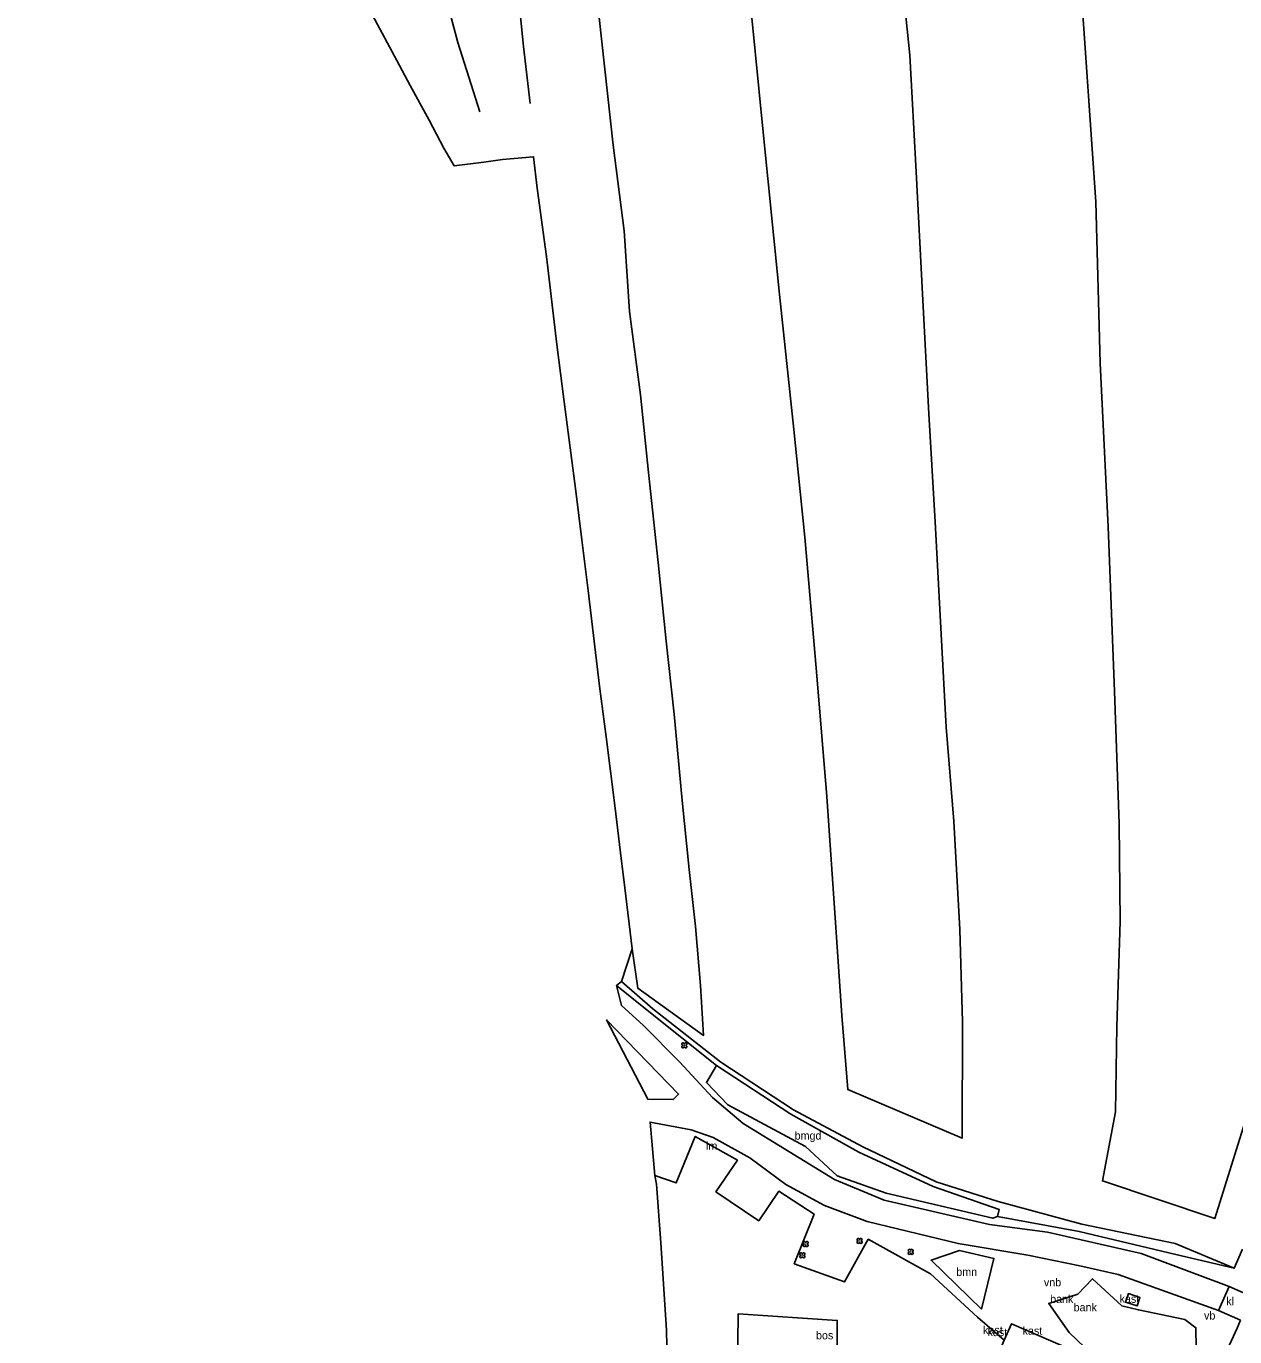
# Model space of a CAD drawing. Extents: x 154825 to 158680, y 370717 to 378075.
# Drawn here: x 158359.2 to 158510.2, y 371215 to 371378.8 of the extents above; entities that cross this region are included whole.
import ezdxf

# ---------------------------------------------------------------- set-up
doc = ezdxf.new("R2010")
doc.units = 0
for name, color, linetype in [('bank(zit)', 7, 'Continuous'), ('boom', 7, 'Continuous'), ('boomgaard(vs)', 7, 'Continuous'), ('boomgroep(vs)', 7, 'Continuous'), ('bos(vs)', 7, 'Continuous'), ('cultuurscheiding', 7, 'Continuous'), ('hoogteverschillijn', 7, 'Continuous'), ('kast_huis punt', 7, 'Continuous'), ('kast_huis(vs)', 7, 'Continuous'), ('klinkerverharding(vs)', 7, 'Continuous'), ('maaiveldlijn algemeen - gesloten verharding', 7, 'Continuous'), ('maaiveldlijn algemeen - onverhard', 7, 'Continuous'), ('maaiveldlijn algemeen - open verharding', 7, 'Continuous'), ('prullen_vuilnisbak', 7, 'Continuous'), ('raster - hek', 7, 'Continuous'), ('talud(boven)', 7, 'Continuous'), ('talud(onder)', 7, 'Continuous'), ('verkeersb_z kabel', 7, 'Continuous'), ('verlichtingsobject', 7, 'Continuous'), ('vlak_akkerland', 7, 'Continuous'), ('vlak_Boomgaard', 7, 'Continuous'), ('vlak_Bos', 7, 'Continuous'), ('vlak_Grazige_vegetatie', 7, 'Continuous')]:
    doc.layers.add(name, color=color, linetype=linetype)

msp = doc.modelspace()

# ---------------------------------------------------------------- linework, layer by layer
at = {"layer": 'boom'}
for centre in [(158441.44, 371251.39), (158456.61, 371226.55), (158463.35, 371226.95), (158456.2, 371225.16), (158469.75, 371225.58)]:
    msp.add_circle(centre, 0.006, dxfattribs=at)
for centre, start, end in [((158441.29, 371251.54), 357.075, 272.925), ((158441.29, 371251.23), 87.075, 2.925), ((158441.6, 371251.54), 267.075, 182.925), ((158441.6, 371251.23), 177.075, 92.925), ((158463.19, 371227.1), 357.075, 272.925), ((158463.51, 371227.1), 267.075, 182.925), ((158456.45, 371226.71), 357.075, 272.925), ((158456.45, 371226.39), 87.075, 2.925), ((158456.77, 371226.71), 267.075, 182.925), ((158456.77, 371226.39), 177.075, 92.925), ((158463.19, 371226.79), 87.075, 2.925), ((158463.51, 371226.79), 177.075, 92.925), ((158469.59, 371225.74), 357.075, 272.925), ((158469.9, 371225.74), 267.075, 182.925), ((158456.04, 371225.31), 357.075, 272.925), ((158456.04, 371225), 87.075, 2.925), ((158456.35, 371225.31), 267.075, 182.925), ((158456.35, 371225), 177.075, 92.925), ((158469.59, 371225.42), 87.075, 2.925), ((158469.9, 371225.42), 177.075, 92.925)]:
    msp.add_arc(centre, 0.158, start, end, dxfattribs=at)
at = {"layer": 'boomgaard(vs)'}
msp.add_lwpolyline([(158480.57, 371229.98), (158479.99, 371229.77), (158466.66, 371232.91), (158460.57, 371235.09), (158456.59, 371238.76), (158446.88, 371243.96), (158444.21, 371246.73), (158445.46, 371248.85)], dxfattribs=at)
at = {"layer": 'boomgroep(vs)'}
msp.add_lwpolyline([(158472.29, 371224.54), (158475.83, 371225.76), (158480.15, 371224.75), (158478.59, 371218.42), (158472.29, 371224.54)], dxfattribs=at)
at = {"layer": 'bos(vs)'}
msp.add_lwpolyline([(158505.46, 371210.98), (158505.38, 371216.1), (158504.02, 371217.11), (158498.2, 371218.32), (158496.11, 371218.82), (158492.47, 371222.22), (158490.65, 371220.31), (158487, 371219.13), (158489.53, 371215.49), (158493.42, 371211.78)], dxfattribs=at)
at = {"layer": 'cultuurscheiding'}
msp.add_lwpolyline([(158510.18, 371223.55), (158511.22, 371225.9)], dxfattribs=at)
at = {"layer": 'hoogteverschillijn'}
for points in [[(158422.2, 371369.09), (158421.35, 371376.21), (158420.37, 371385.83), (158418.64, 371394.89), (158416.42, 371406.68), (158414.15, 371416.2), (158411.27, 371430.04), (158408.7, 371441.22), (158406.63, 371450.16), (158400.46, 371433.08), (158403.35, 371415.45), (158406.03, 371404.61), (158408.36, 371394.38), (158410.5, 371386.6), (158413.14, 371376.71), (158415.9, 371368.08)], [(158449.48, 371384.08), (158451.18, 371366.77), (158453.34, 371345.23), (158455.15, 371328.35), (158456.53, 371314.92), (158457.98, 371298.09), (158459.27, 371282.5), (158460.36, 371266.73), (158461.14, 371255.14), (158461.88, 371245.86), (158476.19, 371239.79), (158476.23, 371254.31), (158475.88, 371265.88), (158475.14, 371279.42), (158474.19, 371291.15), (158473.55, 371302.76), (158472.8, 371316.8), (158471.99, 371330.31), (158471.23, 371345.3), (158470.43, 371360.55), (158469.62, 371375.16), (158468.06, 371390.65)], [(158490.92, 371385.12), (158492.87, 371356.82), (158493.43, 371336.64), (158494.44, 371316.21), (158495.22, 371295.66), (158495.81, 371279.07), (158495.92, 371266.88), (158495.51, 371253.75), (158495.32, 371243.06), (158493.7, 371234.44), (158507.77, 371229.76), (158511.49, 371241.75), (158514.09, 371254.72), (158513.51, 371267.27), (158515.3, 371286.88), (158515.81, 371304.51), (158516.95, 371321.41), (158517.05, 371343.61), (158516.76, 371362.75), (158515.42, 371387.07)], [(158402.49, 371380.14), (158405.53, 371374.48), (158407.19, 371371.37), (158409.54, 371367.04), (158411.41, 371363.51), (158412.68, 371361.33), (158416.4, 371361.77), (158418.71, 371362.11), (158422.61, 371362.45), (158423.07, 371358.54), (158424.21, 371349.97), (158425.5, 371338.99), (158426.42, 371331.81), (158427.87, 371320.66), (158428.64, 371314.55), (158429.41, 371308.24), (158430.28, 371301.19), (158430.85, 371296.28), (158431.66, 371289.93), (158432.76, 371281.37), (158433.47, 371275.45), (158434.01, 371271.06), (158434.93, 371263.45), (158435.62, 371258.52), (158443.86, 371252.63), (158443.45, 371258.89), (158442.84, 371266.23), (158442.04, 371273.38), (158441.16, 371281.99), (158440.17, 371292.77), (158439.16, 371301.9), (158438.16, 371311.74), (158436.98, 371322.99), (158435.97, 371332.69), (158434.59, 371343.11), (158433.91, 371353.21), (158432.54, 371363.89), (158430.42, 371383.3)], [(158437.97, 371234.02), (158438.51, 371226.7), (158439.23, 371215.78), (158439.48, 371203.79)], [(158448.05, 371207.26), (158448.17, 371217.83), (158460.57, 371217), (158460.61, 371206.99)]]:
    msp.add_lwpolyline(points, dxfattribs=at)
at = {"layer": 'kast_huis(vs)'}
msp.add_lwpolyline([(158498.4, 371219.88), (158498.05, 371218.82), (158496.6, 371219.29), (158496.95, 371220.37), (158498.4, 371219.88)], dxfattribs=at)
at = {"layer": 'maaiveldlijn algemeen - gesloten verharding'}
msp.add_lwpolyline([(158510.96, 371217.04), (158510.54, 371216.03), (158507.65, 371209.81), (158503.9, 371202), (158498.42, 371190.4), (158485.48, 371159.9), (158469.54, 371121.29), (158459.26, 371096.34), (158449.43, 371072.22), (158440.37, 371050.33), (158429.63, 371024.46), (158420.28, 371001.66), (158410.56, 370977.79), (158401.63, 370955.89), (158398.29, 370947.78), (158388.67, 370924.63), (158379.26, 370902.09), (158359.19, 370854.15)], dxfattribs=at)
at = {"layer": 'maaiveldlijn algemeen - onverhard'}
for points in [[(158509.53, 371221.24), (158498.54, 371225.36), (158486.82, 371228.02), (158479.6, 371229), (158466.41, 371232.06), (158460.22, 371234.64), (158448.82, 371241.62), (158444.96, 371244.88), (158440.86, 371249.32), (158436.31, 371253.91), (158433.58, 371256.38)], [(158431.74, 371254.56), (158440.72, 371245.3), (158440.06, 371244.61), (158436.9, 371244.66)], [(158437.17, 371241.8), (158442.29, 371240.84), (158445.04, 371239.88), (158449.62, 371237.34), (158454.13, 371233.99), (158458.96, 371231.39), (158464.29, 371229.36), (158475.67, 371226.62), (158484.38, 371225.18), (158490.86, 371223.83), (158495.69, 371222.76), (158508.21, 371218.26)]]:
    msp.add_lwpolyline(points, dxfattribs=at)
at = {"layer": 'maaiveldlijn algemeen - open verharding'}
for points in [[(158509.53, 371221.24), (158508.21, 371218.26)], [(158512.39, 371219.98), (158509.53, 371221.24)], [(158508.21, 371218.26), (158510.96, 371217.04)]]:
    msp.add_lwpolyline(points, dxfattribs=at)
at = {"layer": 'raster - hek'}
for points in [[(158445.46, 371248.85), (158436.6, 371255.94), (158432.97, 371258.85)], [(158445.46, 371248.85), (158454.77, 371242.8), (158463.26, 371238.03), (158472.55, 371233.76), (158480.78, 371230.89), (158480.57, 371229.98)], [(158464.44, 371227.16), (158461.47, 371221.83), (158455.19, 371224.1), (158457.67, 371230.3), (158453.28, 371233.16), (158450.75, 371229.47), (158445.39, 371233.09), (158448.08, 371237.02), (158442.82, 371240.01), (158440.44, 371234.2), (158437.76, 371235.12)], [(158481.43, 371214.55), (158478.08, 371217.43), (158472.21, 371222.83), (158464.44, 371227.16)], [(158464.44, 371227.16), (158464.57, 371227.09)], [(158493.42, 371211.78), (158482.32, 371216.59), (158481.43, 371214.55), (158477.45, 371205.37), (158488.53, 371200.57)]]:
    msp.add_lwpolyline(points, dxfattribs=at)
at = {"layer": 'talud(boven)'}
msp.add_lwpolyline([(158510.18, 371223.55), (158502.89, 371225.24), (158490.8, 371228.13), (158480.57, 371229.98)], dxfattribs=at)
at = {"layer": 'talud(onder)'}
msp.add_lwpolyline([(158510.18, 371223.55), (158502.81, 371226.62), (158491.11, 371229.06), (158480.66, 371231.86), (158472.92, 371234.35), (158463.74, 371238.7), (158455.1, 371243.31), (158446.03, 371249.29), (158437.53, 371255.97), (158433.58, 371259.38)], dxfattribs=at)
at = {"layer": 'vlak_akkerland'}
msp.add_lwpolyline([(158511.22, 371225.9), (158510.18, 371223.55), (158502.81, 371226.62), (158491.11, 371229.06), (158480.66, 371231.86), (158472.92, 371234.35), (158463.74, 371238.7), (158455.1, 371243.31), (158446.03, 371249.29), (158437.53, 371255.97), (158433.58, 371259.38), (158434.93, 371263.45), (158434.01, 371271.06), (158433.47, 371275.45), (158432.76, 371281.37), (158431.66, 371289.93), (158430.85, 371296.28), (158430.28, 371301.19), (158429.41, 371308.24), (158428.64, 371314.55), (158427.87, 371320.66), (158426.42, 371331.81), (158425.5, 371338.99), (158424.21, 371349.97), (158423.07, 371358.54), (158422.61, 371362.45), (158418.71, 371362.11), (158416.4, 371361.77), (158412.68, 371361.33), (158411.41, 371363.51), (158409.54, 371367.04), (158407.19, 371371.37), (158405.53, 371374.48), (158402.49, 371380.14)], dxfattribs=at)
at = {"layer": 'vlak_Boomgaard'}
for points in [[(158480.57, 371229.98), (158479.99, 371229.77), (158466.66, 371232.91), (158460.57, 371235.09), (158456.59, 371238.76), (158446.88, 371243.96), (158444.21, 371246.73), (158445.46, 371248.85), (158454.77, 371242.8), (158463.26, 371238.03), (158472.55, 371233.76), (158480.78, 371230.89)], [(158480.15, 371224.75), (158478.59, 371218.42), (158472.29, 371224.54), (158475.83, 371225.76)]]:
    msp.add_lwpolyline(points, close=True, dxfattribs=at)
at = {"layer": 'vlak_Bos'}
for points in [[(158439.48, 371203.79), (158439.23, 371215.78), (158438.51, 371226.7), (158437.97, 371234.02), (158437.76, 371235.12), (158440.44, 371234.2), (158442.82, 371240.01), (158448.08, 371237.02), (158445.39, 371233.09), (158450.75, 371229.47), (158453.28, 371233.16), (158457.67, 371230.3), (158455.19, 371224.1), (158461.47, 371221.83), (158464.44, 371227.16), (158472.21, 371222.83), (158478.08, 371217.43), (158481.43, 371214.55)], [(158493.42, 371211.78), (158489.53, 371215.49), (158487, 371219.13), (158490.65, 371220.31), (158492.47, 371222.22), (158496.11, 371218.82), (158498.2, 371218.32), (158504.02, 371217.11), (158505.38, 371216.1), (158505.46, 371210.98)]]:
    msp.add_lwpolyline(points, dxfattribs=at)
at = {"layer": 'vlak_Grazige_vegetatie'}
for points in [[(158502.81, 371226.62), (158510.18, 371223.55), (158502.89, 371225.24), (158490.8, 371228.13), (158480.57, 371229.98), (158480.78, 371230.89), (158472.55, 371233.76), (158463.26, 371238.03), (158454.77, 371242.8), (158445.46, 371248.85), (158436.6, 371255.94), (158432.97, 371258.85), (158433.58, 371259.38), (158437.53, 371255.97), (158446.03, 371249.29), (158455.1, 371243.31), (158463.74, 371238.7), (158472.92, 371234.35), (158480.66, 371231.86), (158491.11, 371229.06)], [(158440.72, 371245.3), (158440.06, 371244.61), (158436.9, 371244.66), (158431.74, 371254.56)], [(158472.29, 371224.54), (158478.59, 371218.42), (158480.15, 371224.75), (158475.83, 371225.76)], [(158496.6, 371219.29), (158498.05, 371218.82), (158498.4, 371219.88), (158496.95, 371220.37)]]:
    msp.add_lwpolyline(points, close=True, dxfattribs=at)
for points in [[(158512.39, 371219.98), (158509.53, 371221.24), (158498.54, 371225.36), (158486.82, 371228.02), (158479.6, 371229), (158466.41, 371232.06), (158460.22, 371234.64), (158448.82, 371241.62), (158444.96, 371244.88), (158440.86, 371249.32), (158436.31, 371253.91), (158433.58, 371256.38), (158432.97, 371258.85), (158436.6, 371255.94), (158445.46, 371248.85), (158444.21, 371246.73), (158446.88, 371243.96), (158456.59, 371238.76), (158460.57, 371235.09), (158466.66, 371232.91), (158479.99, 371229.77), (158480.57, 371229.98), (158490.8, 371228.13), (158502.89, 371225.24), (158510.18, 371223.55), (158511.22, 371225.9)], [(158505.46, 371210.98), (158505.38, 371216.1), (158504.02, 371217.11), (158498.2, 371218.32), (158496.11, 371218.82), (158492.47, 371222.22), (158490.65, 371220.31), (158487, 371219.13), (158489.53, 371215.49), (158493.42, 371211.78), (158482.32, 371216.59), (158481.43, 371214.55), (158478.08, 371217.43), (158472.21, 371222.83), (158464.44, 371227.16), (158461.47, 371221.83), (158455.19, 371224.1), (158457.67, 371230.3), (158453.28, 371233.16), (158450.75, 371229.47), (158445.39, 371233.09), (158448.08, 371237.02), (158442.82, 371240.01), (158440.44, 371234.2), (158437.76, 371235.12), (158437.17, 371241.8), (158442.29, 371240.84), (158445.04, 371239.88), (158449.62, 371237.34), (158454.13, 371233.99), (158458.96, 371231.39), (158464.29, 371229.36), (158475.67, 371226.62), (158484.38, 371225.18), (158490.86, 371223.83), (158495.69, 371222.76), (158508.21, 371218.26), (158510.96, 371217.04)], [(158510.54, 371216.03), (158507.65, 371209.81)]]:
    msp.add_lwpolyline(points, dxfattribs=at)

# ---------------------------------------------------------------- texts
at = {"layer": 'bank(zit)'}
for p in [(158487.17, 371219.19), (158490.11, 371218.15)]:
    msp.add_text('bank', height=1, dxfattribs=at).set_placement(p)
at = {"layer": 'boomgaard(vs)'}
msp.add_text('bmgd', height=1, dxfattribs=at).set_placement((158455.24, 371239.61))
at = {"layer": 'boomgroep(vs)'}
msp.add_text('bmn', height=1, dxfattribs=at).set_placement((158475.44, 371222.58))
at = {"layer": 'bos(vs)'}
msp.add_text('bos', height=1, dxfattribs=at).set_placement((158457.91, 371214.65))
at = {"layer": 'kast_huis punt'}
for p in [(158478.79, 371215.31), (158479.35, 371215.05), (158483.73, 371215.22)]:
    msp.add_text('kast', height=1, dxfattribs=at).set_placement(p)
at = {"layer": 'kast_huis(vs)'}
msp.add_text('kast', height=1, dxfattribs=at).set_placement((158495.85, 371219.21))
at = {"layer": 'klinkerverharding(vs)'}
msp.add_text('kl', height=1, dxfattribs=at).set_placement((158509.18, 371218.91))
at = {"layer": 'prullen_vuilnisbak'}
msp.add_text('vnb', height=1, dxfattribs=at).set_placement((158486.39, 371221.27))
at = {"layer": 'verkeersb_z kabel'}
msp.add_text('vb', height=1, dxfattribs=at).set_placement((158506.41, 371217.12))
at = {"layer": 'verlichtingsobject'}
msp.add_text('lm', height=1, dxfattribs=at).set_placement((158444.16, 371238.34))

doc.saveas('drawing.dxf')
